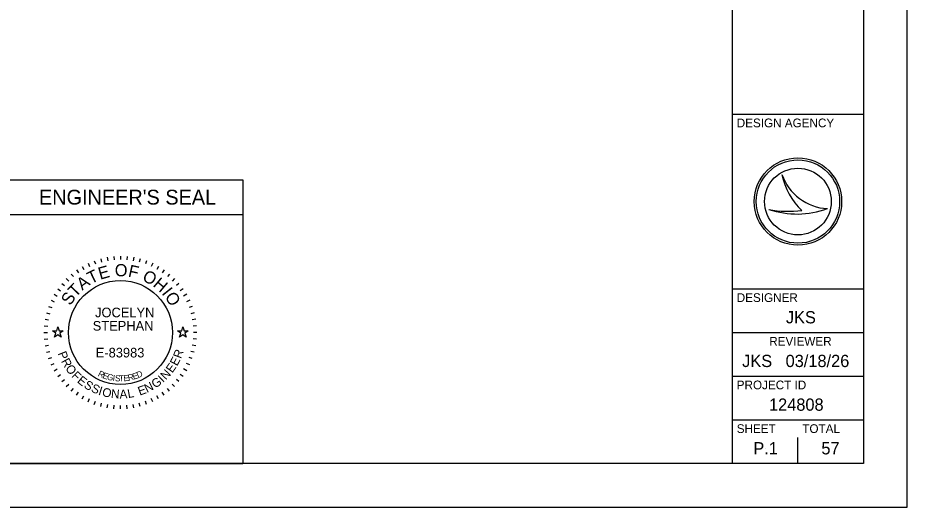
# Model space of a CAD drawing. Extents: x 0 to 34, y 0 to 22.
# Drawn here: x 23.83 to 34, y 0 to 5.6 of the extents above; entities that cross this region are included whole.
import ezdxf

# ---------------------------------------------------------------- set-up
doc = ezdxf.new("R2010")
doc.units = 0
for name, color, linetype in [('SH_Border', 7, 'Continuous'), ('SH_Cut_Line', 7, 'Continuous'), ('SH_Data', 7, 'Continuous'), ('SH_Seal', 7, 'Continuous')]:
    doc.layers.add(name, color=color, linetype=linetype)

msp = doc.modelspace()

# ---------------------------------------------------------------- linework, layer by layer
at = {"layer": 'SH_Border'}
for p, q in [((32, 0.5), (32, 21.5)), ((32, 4.5), (33.5, 4.5)), ((32, 2.5), (33.5, 2.5)), ((32, 2), (33.5, 2)), ((32, 1.5), (33.5, 1.5)), ((32, 1), (33.5, 1))]:
    msp.add_line(p, q, dxfattribs=at)
msp.add_lwpolyline([(1.5, 21.5), (33.5, 21.5), (33.5, 0.5), (1.5, 0.5)], close=True, dxfattribs=at)
at = {"layer": 'SH_Cut_Line'}
msp.add_lwpolyline([(0, 0), (34, 0), (34, 22), (0, 22)], close=True, dxfattribs=at)
at = {"layer": 'SH_Data'}
for p, q in [((32.567, 3.81), (32.567, 3.81)), ((23.6, 3.75), (26.4, 3.75)), ((26.4, 3.75), (26.4, 0.5)), ((32.75, 3.5), (32.75, 3.5)), ((32.417, 3.41), (32.417, 3.41)), ((33.087, 3.419), (33.087, 3.419)), ((23.6, 3.35), (26.4, 3.35)), ((32.75, 0.5), (32.75, 0.8)), ((32.375, 0.675), (32.375, 0.675)), ((23.6, 0.5), (26.4, 0.5))]:
    msp.add_line(p, q, dxfattribs=at)
for radius in [0.5, 0.477, 0.477, 0.382]:
    msp.add_circle((32.75, 3.5), radius, dxfattribs=at)
for centre, radius, start, end in [((33.116, 3.998), 0.58, 198.9257, 198.9319), ((33.347, 3.97), 0.796, 191.6379, 191.6421), ((33.116, 3.998), 0.58, 198.9319, 267.1657), ((33.347, 3.97), 0.796, 191.6421, 226.0947), ((32.739, 4.37), 1.013, 251.4576, 290.0832), ((32.648, 4.654), 1.266, 259.4964, 259.4995), ((32.739, 4.37), 1.013, 251.4527, 251.4576), ((32.648, 4.654), 1.266, 259.4995, 276.6672)]:
    msp.add_arc(centre, radius, start, end, dxfattribs=at)
at = {"layer": 'SH_Seal'}
for p, q in [((24.848, 2.862), (24.855, 2.822)), ((24.924, 2.872), (24.927, 2.832)), ((25, 2.875), (25, 2.835)), ((25.076, 2.872), (25.073, 2.832)), ((25.152, 2.862), (25.145, 2.822)), ((24.563, 2.758), (24.583, 2.723)), ((24.63, 2.793), (24.647, 2.757)), ((24.701, 2.822), (24.714, 2.785)), ((24.774, 2.845), (24.784, 2.807)), ((25.226, 2.845), (25.216, 2.807)), ((25.299, 2.822), (25.286, 2.785)), ((25.37, 2.793), (25.353, 2.757)), ((25.437, 2.758), (25.417, 2.723)), ((24.438, 2.67), (24.463, 2.64)), ((24.498, 2.717), (24.521, 2.684)), ((25.502, 2.717), (25.479, 2.684)), ((25.562, 2.67), (25.537, 2.64)), ((24.33, 2.562), (24.36, 2.537)), ((24.381, 2.619), (24.41, 2.59)), ((25.619, 2.619), (25.59, 2.59)), ((25.67, 2.562), (25.64, 2.537)), ((24.283, 2.502), (24.316, 2.479)), ((25.717, 2.502), (25.684, 2.479)), ((24.207, 2.37), (24.243, 2.353)), ((24.242, 2.438), (24.277, 2.418)), ((25.758, 2.438), (25.723, 2.418)), ((25.793, 2.37), (25.757, 2.353)), ((24.178, 2.299), (24.215, 2.286)), ((25.822, 2.299), (25.785, 2.286)), ((24.138, 2.152), (24.178, 2.145)), ((24.155, 2.226), (24.193, 2.216)), ((25.845, 2.226), (25.807, 2.216)), ((25.862, 2.152), (25.822, 2.145)), ((24.128, 2.076), (24.168, 2.073)), ((25.872, 2.076), (25.832, 2.073)), ((24.125, 2), (24.165, 2)), ((25.875, 2), (25.835, 2)), ((24.128, 1.924), (24.168, 1.927)), ((24.138, 1.848), (24.178, 1.855)), ((25.862, 1.848), (25.822, 1.855)), ((25.872, 1.924), (25.832, 1.927)), ((24.155, 1.774), (24.193, 1.784)), ((25.845, 1.774), (25.807, 1.784)), ((24.178, 1.701), (24.215, 1.714)), ((24.207, 1.63), (24.243, 1.647)), ((25.793, 1.63), (25.757, 1.647)), ((25.822, 1.701), (25.785, 1.714)), ((24.242, 1.563), (24.277, 1.583)), ((25.758, 1.563), (25.723, 1.583)), ((24.283, 1.498), (24.316, 1.521)), ((24.33, 1.438), (24.36, 1.463)), ((25.67, 1.438), (25.64, 1.463)), ((25.717, 1.498), (25.684, 1.521)), ((24.381, 1.381), (24.41, 1.41)), ((24.438, 1.33), (24.463, 1.36)), ((25.562, 1.33), (25.537, 1.36)), ((25.619, 1.381), (25.59, 1.41)), ((24.498, 1.283), (24.521, 1.316)), ((24.563, 1.242), (24.583, 1.277)), ((24.63, 1.207), (24.647, 1.243)), ((25.37, 1.207), (25.353, 1.243)), ((25.437, 1.242), (25.417, 1.277)), ((25.502, 1.283), (25.479, 1.316)), ((24.701, 1.178), (24.714, 1.215)), ((24.774, 1.155), (24.784, 1.193)), ((24.848, 1.138), (24.855, 1.178)), ((24.924, 1.128), (24.927, 1.168)), ((25, 1.125), (25, 1.165)), ((25.076, 1.128), (25.073, 1.168)), ((25.152, 1.138), (25.145, 1.178)), ((25.226, 1.155), (25.216, 1.193)), ((25.299, 1.178), (25.286, 1.215))]:
    msp.add_line(p, q, dxfattribs=at)
for points in [[(24.224, 2.02), (24.271, 2.02), (24.285, 2.065), (24.299, 2.02), (24.346, 2.02), (24.308, 1.992), (24.323, 1.948), (24.285, 1.975), (24.247, 1.948), (24.262, 1.992)], [(25.654, 2.02), (25.701, 2.02), (25.715, 2.065), (25.729, 2.02), (25.776, 2.02), (25.738, 1.992), (25.753, 1.948), (25.715, 1.975), (25.677, 1.948), (25.692, 1.992)]]:
    msp.add_lwpolyline(points, close=True, dxfattribs=at)
msp.add_circle((25, 2), 0.595, dxfattribs=at)

# ---------------------------------------------------------------- texts
at = {"layer": 'SH_Data'}
for s, height, p in [('DESIGN AGENCY', 0.1, (32.05, 4.35)), ("ENGINEER'S SEAL", 0.17, (24.068, 3.465)), ('DESIGNER', 0.1, (32.05, 2.35)), ('JKS', 0.14, (32.612, 2.105)), ('REVIEWER', 0.1, (32.422, 1.85)), ('JKS', 0.14, (32.112, 1.605)), ('03/18/26', 0.14, (32.609, 1.605)), ('PROJECT ID', 0.1, (32.05, 1.35)), ('124808', 0.14, (32.419, 1.105)), ('SHEET', 0.1, (32.05, 0.85)), ('TOTAL', 0.1, (32.8, 0.85)), ('P.1', 0.14, (32.24, 0.605)), ('57', 0.14, (33.018, 0.605))]:
    msp.add_text(s, height=height, dxfattribs=at).set_placement(p)
at = {"layer": 'SH_Seal'}
for s, height, rotation, p in [('E', 0.14, 15.7571, (24.768, 2.604)), ('O', 0.14, 359.7812, (24.935, 2.644)), ('F', 0.14, 347.4362, (25.081, 2.642)), ('T', 0.14, 25.7167, (24.662, 2.552)), ('O', 0.14, 332.2586, (25.24, 2.602)), ('T', 0.14, 46.4344, (24.488, 2.396)), ('A', 0.14, 36.4747, (24.563, 2.478)), ('H', 0.14, 319.9136, (25.363, 2.536)), ('S', 0.14, 57.1924, (24.428, 2.301)), ('I', 0.14, 308.367, (25.466, 2.448)), ('O', 0.14, 303.1491, (25.502, 2.409)), ('P', 0.1, 291.494, (24.282, 1.762)), ('R', 0.1, 69.2322, (25.692, 1.695)), ('R', 0.1, 298.7311, (24.319, 1.672)), ('E', 0.1, 54.758, (25.593, 1.531)), ('E', 0.1, 61.9951, (25.648, 1.61)), ('O', 0.1, 306.4666, (24.365, 1.588)), ('F', 0.1, 314.7068, (24.434, 1.498)), ('R', 0.07, 334.487, (24.737, 1.505)), ('E', 0.07, 341.04, (24.791, 1.48)), ('G', 0.07, 347.4752, (24.841, 1.462)), ('E', 0.07, 17.6836, (25.15, 1.46)), ('D', 0.07, 23.3052, (25.201, 1.477)), ('N', 0.1, 47.0224, (25.52, 1.451)), ('E', 0.1, 321.4393, (24.498, 1.435)), ('S', 0.1, 328.6764, (24.574, 1.375)), ('I', 0.07, 353.7858, (24.909, 1.447)), ('S', 0.07, 356.8926, (24.936, 1.443)), ('T', 0.07, 3.0061, (24.986, 1.439)), ('E', 0.07, 6.0117, (25.039, 1.441)), ('R', 0.07, 11.9184, (25.092, 1.447)), ('N', 0.1, 27.3113, (25.304, 1.308)), ('G', 0.1, 35.0469, (25.398, 1.357)), ('I', 0.1, 43.287, (25.487, 1.421)), ('S', 0.1, 335.9134, (24.656, 1.327)), ('I', 0.1, 343.1505, (24.741, 1.29)), ('O', 0.1, 346.8859, (24.784, 1.275)), ('N', 0.1, 355.1261, (24.889, 1.252)), ('A', 0.1, 2.8617, (24.992, 1.244)), ('L', 0.1, 10.0987, (25.089, 1.249)), ('E', 0.1, 20.0742, (25.221, 1.277))]:
    msp.add_text(s, height=height, rotation=rotation, dxfattribs=at).set_placement(p)
for s, p in [('JOCELYN', (24.71, 2.175)), ('STEPHAN', (24.683, 2.022)), ('E-83983', (24.718, 1.715))]:
    msp.add_text(s, height=0.11, dxfattribs=at).set_placement(p)

doc.saveas('drawing.dxf')
